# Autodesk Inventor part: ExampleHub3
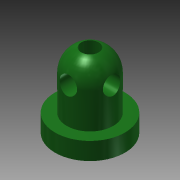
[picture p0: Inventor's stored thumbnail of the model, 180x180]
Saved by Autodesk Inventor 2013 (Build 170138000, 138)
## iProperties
Created: 2013-06
Part Number: ExampleHub3
Material: Generic
Document SubType Name: Modeling
Designer: frankenteddy
Density: 1 g/cm^3
Author: frankenteddy
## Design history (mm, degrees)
sketch "Sketch1"
  geometry: L1 (0, 0)-(0, 10); L2 (0, 0)-(6, 0); L3 (6, 0)-(6, -3); L4 (6, -3)-(0, -3); L5 (0, -3)-(0, 0); L6 (4, 0)-(4, 10); L7 (0, 10)-(4, 6); L8 (0, 10)-(5.657, 10); L9 (0, 2)-(4, 2); C1 r 1.5 at (0, 6); A1 r 4 centre (0, 6) between (4, 6) and (0, 10)
  constraints: 18 end point, 4 point on line, 3 parallel, 2 centre point, 2 horizontal, 2 perpendicular, 2 point on circle, 1 coincident, 1 equal length, 1 tangent, 1 vertical
  dimensions: "d0" = 10 distance of L1.start L1.end; "d1" = 6 distance of L3.end L4.end; "d2" = 3 distance of L2.end L3.end; "d3" = 4 distance between parallel lines of L1 L6; "d4" = 45 deg angle of L7 L8; "d5" = 3 diameter of C1; "d6" = 10 distance of L6.start L6.end; "d14" = 4 distance of L1.end A1.centre (derived); "d22" = 2 distance between parallel lines of L2 L9
revolve "Revolution1" stored, may be unused: angle "d7" = 90 deg
extrude "Extrusion1" cut sketch "Sketch1" stored distance "d8" = 8; taper "d9" = 0 deg
workplane "Work Plane1"
sketch "Sketch2"
  geometry: L1 (0, 0)-(0, 10); C1 r 1.5 at (0, 6)
  constraints: 2 end point, 1 centre point, 1 point on line, 1 vertical
  dimensions: "d11" = 10 distance of L1.start L1.end; "d12" = 3 diameter of C1; "d15" = 4 distance of L1.end C1.centre
extrude "Extrusion2" cut sketch "Sketch2" distance "d16" = 8; taper "d17" = 0 deg
workplane "Work Plane2"
sketch "Sketch3"
  geometry: C1 r 1.5 at (0, 0); 1 further point
  constraints: 1 centre point, 1 coincident
  dimensions: "d19" = 3 diameter of C1
extrude "Extrusion3" cut sketch "Sketch3" distance "d20" = 4; taper "d21" = 0 deg
body "Solid1"
other parameters: "d10" = 4
